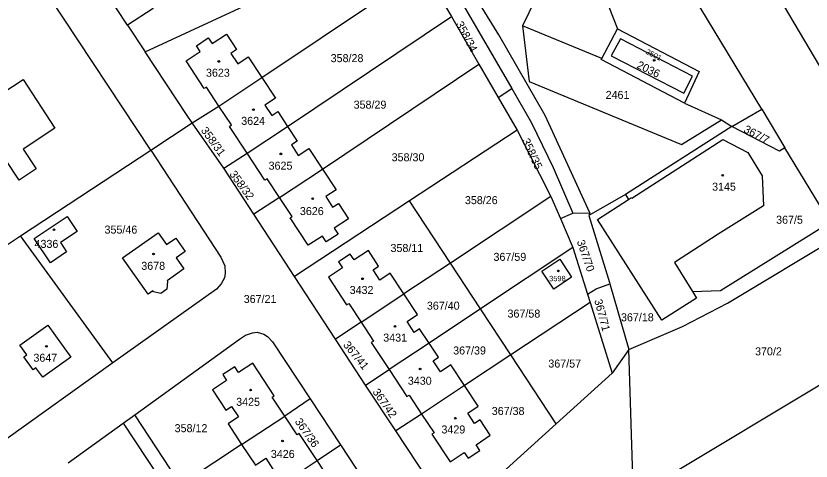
# Model space of a CAD drawing. Extents: x -679220 to -673243, y -1075091 to -1066557.
# Drawn here: x -675822.5 to -675653.7, y -1072766.7 to -1072672.3 of the extents above; entities that cross this region are included whole.
import ezdxf

# ---------------------------------------------------------------- set-up
doc = ezdxf.new("R2010")
doc.units = 0
for name, color, linetype in [('Hranice parcel', 7, 'Continuous'), ('Parcelní čísla', 7, 'Continuous'), ('Značky budov', 7, 'Continuous')]:
    doc.layers.add(name, color=color, linetype=linetype)

msp = doc.modelspace()

# ---------------------------------------------------------------- linework, layer by layer
at = {"layer": 'Hranice parcel'}
for p, q in [((-675793.88, -1072700.75), (-675830.26, -1072645.77)), ((-675770.31, -1072685.33), (-675735.9, -1072662.3)), ((-675730.83, -1072664.33), (-675717.25, -1072687.67)), ((-675651.88, -1072682.89), (-675663.08, -1072664)), ((-675733.57, -1072666.33), (-675730.05, -1072672.42)), ((-675664.18, -1072692.04), (-675679.25, -1072667.1)), ((-675795.06, -1072679.9), (-675771.36, -1072668.86)), ((-675764.83, -1072695.71), (-675730.05, -1072672.42)), ((-675730.05, -1072672.42), (-675724.26, -1072682.51)), ((-675798.81, -1072674.26), (-675795.06, -1072679.9)), ((-675698.13, -1072681.32), (-675715, -1072674.38)), ((-675698.13, -1072681.32), (-675694.79, -1072675.02)), ((-675757.42, -1072704.75), (-675724.26, -1072682.51)), ((-675724.26, -1072682.51), (-675720.12, -1072689.6)), ((-675779.41, -1072691.37), (-675770.31, -1072685.33)), ((-675720.12, -1072689.6), (-675717.25, -1072687.67)), ((-675720.12, -1072689.6), (-675716.1, -1072696.47)), ((-675785.07, -1072694.94), (-675779.41, -1072691.37)), ((-675680.62, -1072690.74), (-675672.72, -1072694.27)), ((-675670.52, -1072695.74), (-675664.18, -1072692.04)), ((-675664.18, -1072692.04), (-675659.26, -1072700.21)), ((-675793.88, -1072700.75), (-675785.07, -1072694.94)), ((-675778.4, -1072704.56), (-675785.07, -1072694.94)), ((-675672.72, -1072694.27), (-675670.52, -1072695.74)), ((-675773.42, -1072701.34), (-675764.83, -1072695.71)), ((-675716.1, -1072696.47), (-675738.93, -1072711.46)), ((-675716.1, -1072696.47), (-675708.95, -1072710.59)), ((-675670.52, -1072695.74), (-675693.12, -1072710.15)), ((-675649.73, -1072716.03), (-675659.26, -1072700.21)), ((-675821.51, -1072718.87), (-675793.88, -1072700.75)), ((-675778.4, -1072704.56), (-675773.42, -1072701.34)), ((-675772.03, -1072714.3), (-675778.4, -1072704.56)), ((-675766.54, -1072710.8), (-675757.42, -1072704.75)), ((-675766.54, -1072710.8), (-675772.03, -1072714.3)), ((-675708.95, -1072710.59), (-675730.24, -1072724.68)), ((-675708.95, -1072710.59), (-675706.93, -1072715.26)), ((-675693.12, -1072710.15), (-675700.86, -1072714.58)), ((-675693.12, -1072710.15), (-675692.46, -1072711.18)), ((-675692.46, -1072711.18), (-675691.86, -1072710.79)), ((-675691.86, -1072710.79), (-675691.77, -1072710.94)), ((-675738.93, -1072711.46), (-675763.37, -1072727.54)), ((-675730.24, -1072724.68), (-675738.93, -1072711.46)), ((-675699.08, -1072715.43), (-675692.46, -1072711.18)), ((-675706.93, -1072715.26), (-675704.28, -1072714.12)), ((-675704.28, -1072714.12), (-675700.65, -1072714.05)), ((-675700.65, -1072714.05), (-675700.86, -1072714.58)), ((-675763.37, -1072727.54), (-675772.03, -1072714.3)), ((-675706.93, -1072715.26), (-675704.28, -1072721.39)), ((-675844.82, -1072734.25), (-675821.51, -1072718.87)), ((-675801.96, -1072745.82), (-675821.51, -1072718.87)), ((-675704.28, -1072721.39), (-675723.86, -1072734.38)), ((-675704.28, -1072721.39), (-675701.19, -1072731.25)), ((-675730.24, -1072724.68), (-675740.15, -1072731.22)), ((-675723.86, -1072734.38), (-675730.24, -1072724.68)), ((-675682.72, -1072724.56), (-675678.86, -1072730.74)), ((-675754.67, -1072740.83), (-675763.37, -1072727.54)), ((-675696.41, -1072729.09), (-675692.39, -1072742.99)), ((-675678.86, -1072730.74), (-675678.02, -1072732.09)), ((-675749.25, -1072737.23), (-675740.15, -1072731.22)), ((-675701.19, -1072731.25), (-675700.64, -1072733.02)), ((-675723.86, -1072734.38), (-675734.81, -1072741.63)), ((-675717.44, -1072744.15), (-675723.86, -1072734.38)), ((-675700.64, -1072733.02), (-675717.44, -1072744.15)), ((-675700.64, -1072733.02), (-675695.96, -1072748.03)), ((-675749.25, -1072737.23), (-675754.67, -1072740.83)), ((-675748.27, -1072750.54), (-675754.67, -1072740.83)), ((-675634.82, -1072740.31), (-675691.64, -1072774.4)), ((-675734.81, -1072741.63), (-675743.3, -1072747.25)), ((-675717.44, -1072744.15), (-675727.29, -1072750.66)), ((-675707.81, -1072758.79), (-675717.44, -1072744.15)), ((-675692.39, -1072742.99), (-675695.96, -1072748.03)), ((-675801.96, -1072745.82), (-675824.66, -1072762.08)), ((-675748.27, -1072750.54), (-675743.3, -1072747.25)), ((-675695.96, -1072748.03), (-675707.81, -1072758.79)), ((-675741.85, -1072760.26), (-675748.27, -1072750.54)), ((-675727.29, -1072750.66), (-675736.41, -1072756.69)), ((-675760.01, -1072753.46), (-675765.43, -1072757.13)), ((-675760.01, -1072753.46), (-675753.6, -1072763.19)), ((-675799.71, -1072758.62), (-675797.28, -1072756.88)), ((-675787.54, -1072771.64), (-675797.28, -1072756.88)), ((-675774.59, -1072763.14), (-675765.43, -1072757.13)), ((-675736.41, -1072756.69), (-675741.85, -1072760.26)), ((-675811.39, -1072767.03), (-675799.71, -1072758.62)), ((-675732.75, -1072774), (-675741.85, -1072760.26)), ((-675774.59, -1072763.14), (-675787.54, -1072771.64)), ((-675758.58, -1072766.54), (-675753.6, -1072763.19)), ((-675753.6, -1072763.19), (-675747.19, -1072772.92)), ((-675767.08, -1072772.15), (-675758.58, -1072766.54))]:
    msp.add_line(p, q, dxfattribs=at)
for points in [[(-675705.54, -1072635.75), (-675703.56, -1072652.66), (-675694.79, -1072675.02)], [(-675711.53, -1072639.04), (-675708.25, -1072660.5), (-675715, -1072674.38)], [(-675700.65, -1072714.05), (-675705.76, -1072702.93), (-675710.18, -1072693.37), (-675720.03, -1072676.29), (-675728.35, -1072662.68), (-675735.05, -1072651.95)], [(-675796.86, -1072665.66), (-675793.4, -1072670.71), (-675798.81, -1072674.26)], [(-675847.47, -1072667.16), (-675839.57, -1072679.99), (-675849.4, -1072686.69), (-675841.4, -1072699.09), (-675820.99, -1072685.76), (-675814.27, -1072696.09), (-675820.97, -1072700.52), (-675818.2, -1072704.71), (-675821.84, -1072707.11), (-675824.6, -1072702.93), (-675834.87, -1072709.72), (-675831.37, -1072715.02), (-675841.76, -1072721.9), (-675860.16, -1072693.73), (-675870.46, -1072700.46), (-675878.83, -1072687.64)], [(-675798.81, -1072674.26), (-675801.17, -1072670.66), (-675802.19, -1072669.17)], [(-675715, -1072674.38), (-675713.53, -1072686.15), (-675681.24, -1072699.51), (-675672.72, -1072694.27)], [(-675694.79, -1072675.02), (-675677.44, -1072684.03), (-675680.62, -1072690.74)], [(-675779.41, -1072691.37), (-675782.07, -1072687.41), (-675782.52, -1072687.65), (-675786.38, -1072681.81), (-675783.38, -1072679.79), (-675784.18, -1072678.59), (-675781.68, -1072676.91), (-675780.83, -1072678.13), (-675777.83, -1072676.13), (-675775.68, -1072679.39), (-675776.87, -1072680.22), (-675775.42, -1072682.4), (-675773.23, -1072680.94), (-675770.31, -1072685.33)], [(-675678.89, -1072685.03), (-675694.2, -1072677.12), (-675696.12, -1072680.74), (-675680.76, -1072688.64), (-675678.89, -1072685.03)], [(-675785.07, -1072694.94), (-675786.13, -1072693.37), (-675795.06, -1072679.9)], [(-675680.62, -1072690.74), (-675698.26, -1072681.54), (-675698.13, -1072681.32)], [(-675770.31, -1072685.33), (-675767.41, -1072689.69), (-675769.63, -1072691.18), (-675768.16, -1072693.36), (-675766.93, -1072692.56), (-675764.83, -1072695.71)], [(-675717.25, -1072687.67), (-675713.07, -1072694.97), (-675708.43, -1072704.41), (-675704.28, -1072714.12)], [(-675773.42, -1072701.34), (-675777.2, -1072695.69), (-675776.74, -1072695.39), (-675779.41, -1072691.37)], [(-675764.83, -1072695.71), (-675762.77, -1072698.83), (-675764.02, -1072699.62), (-675762.57, -1072701.88), (-675760.31, -1072700.37), (-675757.42, -1072704.75)], [(-675659.26, -1072700.21), (-675660.41, -1072700.94), (-675670.52, -1072695.74)], [(-675691.77, -1072710.94), (-675672.43, -1072698.46), (-675667.17, -1072701.25), (-675664.11, -1072706.21), (-675663.81, -1072712.52)], [(-675793.88, -1072700.75), (-675778.99, -1072723.46), (-675778.19, -1072725.29), (-675778.06, -1072726.79), (-675778.21, -1072727.8), (-675778.91, -1072729.11), (-675779.89, -1072730.24), (-675801.96, -1072745.82)], [(-675766.54, -1072710.8), (-675769.2, -1072706.79), (-675769.67, -1072707.09), (-675773.42, -1072701.34)], [(-675757.42, -1072704.75), (-675754.51, -1072709.12), (-675756.75, -1072710.59), (-675755.27, -1072712.84), (-675754.03, -1072712.01), (-675751.9, -1072715.27), (-675754.92, -1072717.27), (-675754.11, -1072718.52), (-675756.62, -1072720.19), (-675757.45, -1072718.95), (-675760.47, -1072720.9), (-675764.31, -1072715.09), (-675763.87, -1072714.8), (-675766.54, -1072710.8)], [(-675663.81, -1072712.52), (-675673.41, -1072718.52), (-675682.72, -1072724.56)], [(-675815.17, -1072724.6), (-675818.62, -1072719.44), (-675811.65, -1072714.8), (-675809.47, -1072717.96), (-675813.06, -1072720.34), (-675811.74, -1072722.31), (-675815.17, -1072724.6)], [(-675700.86, -1072714.58), (-675696.49, -1072728.8), (-675696.41, -1072729.09)], [(-675678.02, -1072732.09), (-675685.39, -1072736.81), (-675699.08, -1072715.43)], [(-675678.86, -1072730.74), (-675672.92, -1072730.51), (-675649.87, -1072716.12), (-675649.73, -1072716.03)], [(-675786.85, -1072725.89), (-675790.43, -1072728.44), (-675790.34, -1072728.59), (-675790.46, -1072730.22), (-675791.76, -1072731.14), (-675793.29, -1072730.76), (-675793.41, -1072730.57), (-675794.46, -1072731.26), (-675799.88, -1072723.56), (-675792.31, -1072718.24), (-675790.53, -1072720.77), (-675788.55, -1072719.37), (-675786.56, -1072722.19), (-675788.51, -1072723.57), (-675786.85, -1072725.89)], [(-675692.39, -1072742.99), (-675681.03, -1072738.1), (-675671.48, -1072733.15), (-675647.93, -1072719.02)], [(-675740.15, -1072731.22), (-675743.04, -1072726.84), (-675745.25, -1072728.29), (-675746.7, -1072726.09), (-675745.51, -1072725.3), (-675747.66, -1072722.04), (-675750.67, -1072724.02), (-675751.52, -1072722.78), (-675754.02, -1072724.42), (-675753.21, -1072725.69), (-675756.18, -1072727.7), (-675752.35, -1072733.53), (-675751.87, -1072733.23), (-675749.25, -1072737.23)], [(-675708.35, -1072730.2), (-675710.87, -1072726.4), (-675707.06, -1072723.87), (-675704.56, -1072727.65), (-675708.35, -1072730.2)], [(-675701.19, -1072731.25), (-675699.31, -1072730.11), (-675696.41, -1072729.09)], [(-675734.81, -1072741.63), (-675736.8, -1072738.65), (-675737.95, -1072739.4), (-675739.46, -1072737.06), (-675737.25, -1072735.59), (-675740.15, -1072731.22)], [(-675810.82, -1072744.63), (-675816.8, -1072748.88), (-675818.26, -1072746.87), (-675818.87, -1072747.3), (-675820.8, -1072744.55), (-675820.2, -1072744.13), (-675821.64, -1072742.07), (-675815.71, -1072737.83), (-675810.82, -1072744.63)], [(-675749.25, -1072737.23), (-675746.63, -1072741.22), (-675747.08, -1072741.52), (-675743.3, -1072747.25)], [(-675797.28, -1072756.88), (-675775.04, -1072740.81), (-675773.74, -1072739.94), (-675772.31, -1072739.44), (-675771.32, -1072739.3), (-675769.88, -1072739.72), (-675769.07, -1072740.28), (-675768.06, -1072741.39), (-675760.01, -1072753.46)], [(-675727.29, -1072750.66), (-675730.2, -1072746.29), (-675732.4, -1072747.72), (-675733.92, -1072745.42), (-675732.82, -1072744.66), (-675734.81, -1072741.63)], [(-675691.64, -1072774.4), (-675691.49, -1072772.19), (-675692.39, -1072742.99)], [(-675765.43, -1072757.13), (-675768.08, -1072753.13), (-675767.65, -1072752.81), (-675772.19, -1072745.92), (-675775.23, -1072747.91), (-675776.06, -1072746.68), (-675778.59, -1072748.34), (-675777.77, -1072749.58), (-675780.77, -1072751.58), (-675777.94, -1072755.9), (-675776.72, -1072755.11), (-675775.28, -1072757.28), (-675777.48, -1072758.74), (-675774.59, -1072763.14)], [(-675743.3, -1072747.25), (-675739.5, -1072753), (-675739.05, -1072752.7), (-675736.41, -1072756.69)], [(-675736.41, -1072756.69), (-675733.75, -1072760.66), (-675734.21, -1072760.96), (-675730.34, -1072766.83), (-675727.34, -1072764.84), (-675726.49, -1072766.08), (-675724, -1072764.4), (-675724.82, -1072763.19), (-675721.8, -1072761.18), (-675723.98, -1072757.91), (-675725.17, -1072758.69), (-675726.61, -1072756.51), (-675724.41, -1072755.04), (-675727.29, -1072750.66)], [(-675758.58, -1072766.54), (-675762.36, -1072760.81), (-675762.82, -1072761.11), (-675765.43, -1072757.13)], [(-675799.71, -1072758.62), (-675781.98, -1072785.51), (-675792.11, -1072793.7)], [(-675707.81, -1072758.79), (-675726, -1072775.25), (-675729.53, -1072776.19), (-675732.75, -1072774)], [(-675774.59, -1072763.14), (-675771.68, -1072767.54), (-675769.47, -1072766.07), (-675767.94, -1072768.39), (-675769.07, -1072769.13), (-675767.08, -1072772.15)], [(-675752.62, -1072776.58), (-675755.26, -1072772.58), (-675754.81, -1072772.26), (-675758.58, -1072766.54)]]:
    msp.add_lwpolyline(points, dxfattribs=at)
at = {"layer": 'Značky budov'}
for centre in [(-675779.44, -1072681.93), (-675687.01, -1072681.67), (-675772.08, -1072692.15), (-675766.26, -1072701.53), (-675672.47, -1072706.06), (-675759.5, -1072711.03), (-675814.43, -1072717.62), (-675793.29, -1072722.76), (-675707.36, -1072726.33), (-675748.93, -1072728.01), (-675742.05, -1072738.11), (-675816.02, -1072742.32), (-675736.71, -1072747.13), (-675772.68, -1072751.61), (-675729.23, -1072757.58), (-675765.91, -1072762.42)]:
    msp.add_circle(centre, 0.175, dxfattribs=at)

# ---------------------------------------------------------------- texts
at = {"layer": 'Parcelní čísla'}
for s, height, rotation, p in [('358/34', 1.7, 298, (-675729.19, -1072673.96)), ('2501', 1.14, 333, (-675688.92, -1072680.24)), ('2036', 1.7, 334, (-675690.86, -1072683.24)), ('367/7', 1.7, 332, (-675668.19, -1072696.82)), ('358/31', 1.7, 306, (-675783.33, -1072696.57)), ('358/35', 1.7, 295, (-675715.12, -1072698.71)), ('358/32', 1.7, 306, (-675777.27, -1072705.83)), ('367/70', 1.7, 289, (-675703.47, -1072720.1)), ('367/71', 1.7, 285, (-675699.76, -1072732.58)), ('367/41', 1.7, 309, (-675753.15, -1072742.08)), ('367/42', 1.7, 305, (-675746.89, -1072752.02)), ('367/36', 1.7, 305, (-675763.39, -1072758.28))]:
    msp.add_text(s, height=height, rotation=rotation, dxfattribs=at).set_placement(p)
for s, height, p in [('358/28', 1.7, (-675755.69, -1072682.07)), ('3623', 1.7, (-675782.16, -1072685.16)), ('2461', 1.7, (-675697.33, -1072689.87)), ('358/29', 1.7, (-675750.82, -1072691.93)), ('3624', 1.7, (-675774.68, -1072695.37)), ('358/30', 1.7, (-675742.75, -1072703.09)), ('3625', 1.7, (-675768.87, -1072704.87)), ('3145', 1.7, (-675674.73, -1072709.33)), ('358/26', 1.7, (-675727.2, -1072712.18)), ('3626', 1.7, (-675762.22, -1072714.5)), ('367/5', 1.7, (-675661.14, -1072716.34)), ('355/46', 1.7, (-675803.69, -1072718.43)), ('4336', 1.7, (-675818.55, -1072721.46)), ('358/11', 1.7, (-675742.99, -1072722.33)), ('367/59', 1.7, (-675721.13, -1072724.21)), ('3678', 1.7, (-675795.89, -1072726.11)), ('3598', 1.14, (-675709.31, -1072728.53)), ('3432', 1.7, (-675751.66, -1072731.24)), ('367/21', 1.7, (-675774.15, -1072733.14)), ('367/40', 1.7, (-675735.27, -1072734.56)), ('367/58', 1.7, (-675718.15, -1072736.24)), ('367/18', 1.7, (-675694.07, -1072737.02)), ('3431', 1.7, (-675744.53, -1072741.33)), ('367/39', 1.7, (-675729.69, -1072744.06)), ('370/2', 1.7, (-675665.61, -1072744.25)), ('3647', 1.7, (-675818.79, -1072745.6)), ('367/57', 1.7, (-675709.49, -1072746.84)), ('3430', 1.7, (-675739.31, -1072750.48)), ('3425', 1.7, (-675775.75, -1072754.95)), ('367/38', 1.7, (-675721.5, -1072756.89)), ('358/12', 1.7, (-675788.81, -1072760.54)), ('3429', 1.7, (-675732.18, -1072760.81)), ('3426', 1.7, (-675768.39, -1072766))]:
    msp.add_text(s, height=height, dxfattribs=at).set_placement(p)

doc.saveas('drawing.dxf')
